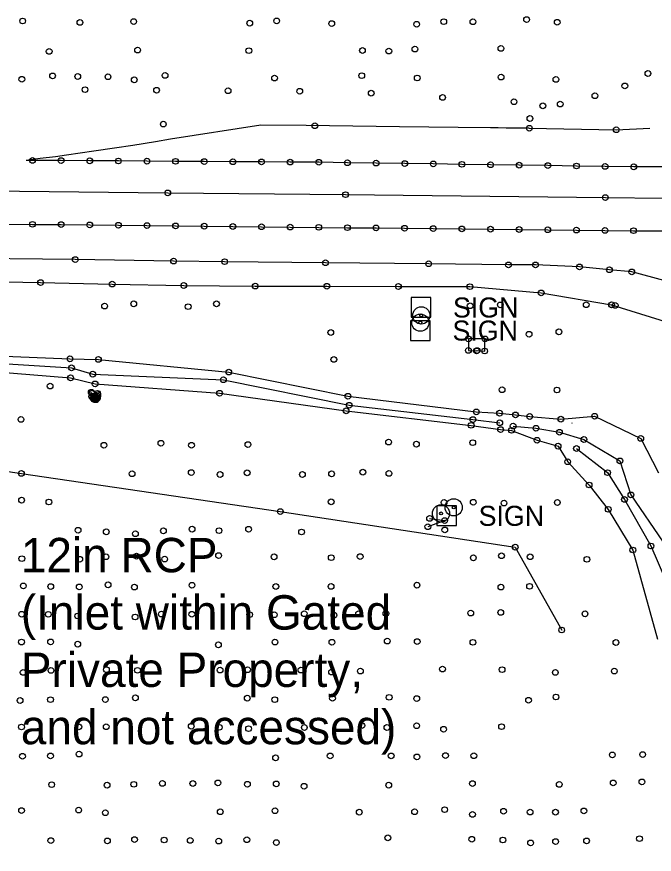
# Model space of a CAD drawing. Extents: x 20503438 to 20508873, y 7964251 to 7984667.
# Drawn here: x 20505829.6 to 20506052.3, y 7970315.8 to 7970608.1 of the extents above; entities that cross this region are included whole.
import ezdxf

# ---------------------------------------------------------------- set-up
doc = ezdxf.new("R2010")
doc.units = 0
for name, color, linetype in [('SurBreakLine', 7, 'Continuous'), ('SurConcreteSlab', 7, 'Continuous'), ('SurDrainageArrowDown', 7, 'Continuous'), ('SurDrainageArrowUp', 7, 'Continuous'), ('SurEdgeShoulderPaved', 7, 'Continuous'), ('SurEdgeShoulderUnpaved', 7, 'Continuous'), ('SurFenceChainLink', 7, 'Continuous'), ('SurMiscStructureLine', 7, 'Continuous'), ('SurPointsNonDTM', 7, 'Continuous'), ('SurRoadPoints', 7, 'Continuous'), ('SurSurveyPoints', 7, 'Continuous'), ('SurTopOfWater', 7, 'Continuous'), ('SurTxtDrainage', 7, 'Continuous')]:
    doc.layers.add(name, color=color, linetype=linetype)

msp = doc.modelspace()

# ---------------------------------------------------------------- linework, layer by layer
at = {"layer": 'SurBreakLine'}
for points in [[(20505659.98, 7970549.19), (20505725.91, 7970548.38), (20505788.99, 7970547.63), (20505882.34, 7970546.59), (20505944.46, 7970545.97), (20506035.17, 7970544.95), (20506055.65, 7970544.73), (20506135.76, 7970544.03), (20506246.7, 7970542.7), (20506314.1, 7970541.94), (20506377.13, 7970541.22), (20506448.59, 7970540.63), (20506494, 7970540.08), (20506513.48, 7970539.53), (20506534.35, 7970539.62)], [(20505710.77, 7970497.54), (20505732.85, 7970495.46), (20505756.48, 7970493.37), (20505802.57, 7970490.52), (20505848.21, 7970488.68), (20505858.14, 7970488.46), (20505903.67, 7970484.04), (20505945.27, 7970475.61), (20505990.11, 7970470.17), (20505998.24, 7970469.71), (20506003.81, 7970469.11), (20506008.75, 7970468.56), (20506019.64, 7970467.63), (20506031.44, 7970468.66), (20506047.52, 7970460.92), (20506053.76, 7970448.87)], [(20505711.46, 7970490.59), (20505731.01, 7970491.18), (20505758.81, 7970489.68), (20505801.32, 7970485.94), (20505848.43, 7970482.04), (20505856.97, 7970479.93), (20505900.46, 7970476.68), (20505944.64, 7970470.53), (20505988.31, 7970465.47), (20505998.59, 7970464), (20506002.44, 7970463.73), (20506011.31, 7970460.28), (20506018.66, 7970458.21), (20506022.02, 7970452.76), (20506029.51, 7970444.65), (20506036.2, 7970436.16), (20506044.77, 7970421.97), (20506053.42, 7970390.9)], [(20505857.84, 7970475.58), (20505857.72, 7970474.82), (20505857.29, 7970474.41), (20505856.69, 7970474.5), (20505856.27, 7970474.81), (20505855.82, 7970475.52), (20505855.65, 7970477.02)], [(20506002.96, 7970465.21), (20506010.95, 7970464.45), (20506019.15, 7970463.07), (20506027.69, 7970460.54), (20506040.26, 7970453.07), (20506044.1, 7970441.21), (20506055.37, 7970424.69), (20506067.63, 7970400.85), (20506090.73, 7970364.86), (20506121.5, 7970310.22), (20506143.59, 7970262.18), (20506176.03, 7970210.91), (20506203.05, 7970164.06), (20506235.78, 7970108.78), (20506259.31, 7970069.25), (20506303.96, 7969999.09)]]:
    msp.add_lwpolyline(points, dxfattribs=at)
at = {"layer": 'SurConcreteSlab'}
for points in [[(20506008.62, 7970569.15), (20506005.9, 7970569.17), (20506000.48, 7970569.22), (20505997.76, 7970569.24), (20505995.05, 7970569.27), (20505983.76, 7970569.4), (20505963.23, 7970569.67), (20505930.73, 7970570.05), (20505914.91, 7970570.2), (20505883.34, 7970565.3), (20505878.07, 7970564.42), (20505870.19, 7970563.15), (20505863.71, 7970562.15), (20505856.57, 7970561.09), (20505847.04, 7970559.75), (20505843.1, 7970559.22), (20505837.75, 7970558.53), (20505832.94, 7970557.93)], [(20506008.62, 7970569.15), (20506038.99, 7970568.62), (20506050.68, 7970569.22)], [(20506055.09, 7970555.65), (20506045.09, 7970555.68), (20506035.09, 7970555.82), (20506025.09, 7970555.97), (20506015.09, 7970556.11), (20506005.09, 7970556.26), (20505995.09, 7970556.4), (20505985.09, 7970556.55), (20505975.09, 7970556.69), (20505965.1, 7970556.83), (20505955.1, 7970556.98), (20505945.1, 7970557.12), (20505935.1, 7970557.26), (20505925.1, 7970557.32), (20505915.1, 7970557.39), (20505905.1, 7970557.45), (20505895.1, 7970557.52), (20505885.1, 7970557.59), (20505875.1, 7970557.65), (20505865.1, 7970557.72), (20505855.1, 7970557.78), (20505845.1, 7970557.85), (20505835.1, 7970557.92), (20505832.94, 7970557.93)], [(20505825.12, 7970535.72), (20505835.12, 7970535.61), (20505845.11, 7970535.51), (20505855.11, 7970535.4), (20505865.11, 7970535.3), (20505875.1, 7970535.19), (20505885.1, 7970535.08), (20505895.1, 7970534.98), (20505905.09, 7970534.87), (20505915.09, 7970534.77), (20505925.09, 7970534.66), (20505935.08, 7970534.56), (20505945.08, 7970534.45), (20505955.08, 7970534.35), (20505965.07, 7970534.24), (20505975.07, 7970534.14), (20505985.07, 7970534.03), (20505995.06, 7970533.92), (20506005.06, 7970533.82), (20506015.05, 7970533.71), (20506025.05, 7970533.61), (20506035.05, 7970533.5), (20506045.04, 7970533.4), (20506055.04, 7970533.3)], [(20505857.77, 7970476.64), (20505857.55, 7970475.22), (20505857.26, 7970474.83), (20505856.78, 7970474.8), (20505856.5, 7970474.91), (20505855.89, 7970476.65), (20505855.88, 7970475.71), (20505856.35, 7970474.81), (20505856.92, 7970474.72), (20505857.33, 7970474.73), (20505857.65, 7970474.96), (20505857.81, 7970475.61), (20505857.92, 7970476.17)]]:
    msp.add_lwpolyline(points, dxfattribs=at)
msp.add_lwpolyline([(20505993.14, 7970495.64), (20505987.36, 7970495.62), (20505987.35, 7970491.61), (20505990.21, 7970491.44), (20505990.39, 7970491.57), (20505993.03, 7970491.41)], close=True, dxfattribs=at)
at = {"layer": 'SurDrainageArrowDown'}
msp.add_lwpolyline([(20506025.08, 7970457.4), (20506035.95, 7970448.96), (20506041.86, 7970439.61), (20506051.09, 7970423.37), (20506062.05, 7970398.08), (20506083.83, 7970361.77), (20506117.02, 7970306.88), (20506136.1, 7970258.71), (20506172.77, 7970209.71), (20506199.46, 7970161.39), (20506230.82, 7970104.99), (20506255.2, 7970065.03), (20506302.09, 7969997.91), (20506332.16, 7969947.08), (20506370.3, 7969883.15), (20506398.2, 7969834.55), (20506432.94, 7969784.54)], dxfattribs=at)
at = {"layer": 'SurDrainageArrowUp'}
msp.add_lwpolyline([(20505588.51, 7970507.81), (20505597.53, 7970506.94), (20505614.51, 7970502.19), (20505635.08, 7970498.83), (20505655.93, 7970496.49), (20505678.23, 7970494.58), (20505682.9, 7970493.73), (20505711.11, 7970493.62), (20505731.16, 7970493.62), (20505757.46, 7970492.01), (20505802.13, 7970488.46), (20505848.74, 7970485.55), (20505856.14, 7970483.32), (20505901.79, 7970481.39), (20505945.72, 7970472.48), (20505988.92, 7970467.48), (20505998.29, 7970466.36)], dxfattribs=at)
at = {"layer": 'SurEdgeShoulderPaved'}
msp.add_lwpolyline([(20506056.08, 7970515.88), (20506044.41, 7970519.01), (20506036.59, 7970519.75), (20506026.15, 7970520.74), (20506010.77, 7970521.44), (20506001.36, 7970521.44), (20505973.47, 7970521.86), (20505937.45, 7970522.2), (20505902.22, 7970522.58), (20505884.4, 7970522.79), (20505850.04, 7970523.3), (20505804.42, 7970523.81), (20505772.68, 7970524.16), (20505723.75, 7970524.74), (20505698.34, 7970525.01)], dxfattribs=at)
at = {"layer": 'SurEdgeShoulderUnpaved'}
msp.add_lwpolyline([(20505583.75, 7970522.72), (20505588.05, 7970521.67), (20505613.04, 7970520.89), (20505638.02, 7970520.1), (20505663.01, 7970519.31), (20505687.99, 7970518.52), (20505712.98, 7970517.9), (20505737.97, 7970517.38), (20505762.96, 7970516.86), (20505787.95, 7970516.34), (20505812.95, 7970515.82), (20505837.94, 7970515.3), (20505862.93, 7970514.78), (20505887.92, 7970514.26), (20505912.91, 7970514.05), (20505937.9, 7970513.99), (20505962.89, 7970513.93), (20505987.89, 7970513.87), (20506012.76, 7970511.67), (20506037.35, 7970507.53), (20506060.92, 7970500.21), (20506079.1, 7970483.65), (20506094.14, 7970463.86), (20506101.05, 7970448.2)], dxfattribs=at)
at = {"layer": 'SurFenceChainLink'}
msp.add_lwpolyline([(20505563.79, 7970488.13), (20505618.36, 7970480.42), (20505698.84, 7970468.55), (20505760.89, 7970459.22), (20505831.24, 7970448.68), (20505921.66, 7970435.36), (20506003.71, 7970422.97), (20506019.92, 7970394.05)], dxfattribs=at)
at = {"layer": 'SurMiscStructureLine'}
msp.add_lwpolyline([(20505973.8, 7970432.99), (20505979.06, 7970432.22), (20505973.17, 7970430.1)], dxfattribs=at)
at = {"layer": 'SurPointsNonDTM'}
for centre in [(20505831.24, 7970448.68), (20505921.66, 7970435.36), (20505973.8, 7970432.99), (20505979.06, 7970432.22), (20505973.17, 7970430.1), (20506003.71, 7970422.97), (20506019.92, 7970394.05)]:
    msp.add_circle(centre, 1, dxfattribs=at)
at = {"layer": 'SurRoadPoints'}
for points in [[(20505970.75, 7970503.17), (20505970.75, 7970503.17), (20505974.18, 7970503.17), (20505974.18, 7970510.03), (20505967.32, 7970510.03), (20505967.32, 7970503.17), (20505970.75, 7970503.17)], [(20505970.57, 7970495.12), (20505970.57, 7970495.12), (20505974, 7970495.12), (20505974, 7970501.98), (20505967.14, 7970501.98), (20505967.14, 7970495.12), (20505970.57, 7970495.12)], [(20505979.71, 7970430.47), (20505979.71, 7970430.47), (20505983.14, 7970430.47), (20505983.14, 7970437.33), (20505976.28, 7970437.33), (20505976.28, 7970430.47), (20505979.71, 7970430.47)]]:
    msp.add_lwpolyline(points, dxfattribs=at)
for centre, radius in [((20505970.89, 7970503.83), 3), ((20505970.56, 7970501.31), 3), ((20505970.89, 7970503.83), 0.5), ((20505970.56, 7970501.31), 0.5), ((20505982.21, 7970436.84), 3), ((20505977.79, 7970434.74), 3), ((20505977.79, 7970434.74), 0.5), ((20505982.21, 7970436.84), 0.5)]:
    msp.add_circle(centre, radius, dxfattribs=at)
at = {"layer": 'SurSurveyPoints'}
for centre in [(20506007.66, 7970607.05), (20505831.68, 7970606.57), (20505851.69, 7970606.06), (20505870.45, 7970606.36), (20505910.98, 7970605.82), (20505920.39, 7970606.6), (20505939.61, 7970605.65), (20505969.28, 7970605.44), (20505978.72, 7970606.33), (20505988.93, 7970606.3), (20506018.36, 7970606.13), (20505840.94, 7970595.96), (20505871.82, 7970596.41), (20505910.66, 7970596.21), (20505950.35, 7970596.28), (20505959.55, 7970596.07), (20505968.68, 7970596.77), (20505998.7, 7970597.02), (20505831.39, 7970586.25), (20505842.14, 7970587.42), (20505850.92, 7970587.21), (20505861.48, 7970587.1), (20505881.4, 7970587.59), (20505919.64, 7970586.64), (20505950.09, 7970587.5), (20505969.48, 7970586.67), (20505998.76, 7970587), (20506017.91, 7970586.19), (20506050.04, 7970588.24), (20505870.66, 7970586.04), (20506041.98, 7970583.9), (20505853.45, 7970582.6), (20505878.44, 7970582.42), (20505903.43, 7970582.24), (20505928.43, 7970582.06), (20505953.4, 7970581.38), (20506031.53, 7970580.5), (20505978.34, 7970579.89), (20506003.27, 7970578.4), (20506019.41, 7970577.58), (20506013.34, 7970576.96), (20506008.82, 7970572.55), (20505880.8, 7970570.58), (20505933.71, 7970570.02), (20506008.62, 7970569.15), (20506008.62, 7970569.15), (20506038.99, 7970568.62), (20505835.1, 7970557.92), (20505845.1, 7970557.85), (20505855.1, 7970557.78), (20505865.1, 7970557.72), (20505875.1, 7970557.65), (20505885.1, 7970557.59), (20505895.1, 7970557.52), (20505905.1, 7970557.45), (20505915.1, 7970557.39), (20505925.1, 7970557.32), (20505935.1, 7970557.26), (20505945.1, 7970557.12), (20505955.1, 7970556.98), (20505965.1, 7970556.83), (20505975.09, 7970556.69), (20505985.09, 7970556.55), (20505995.09, 7970556.4), (20506005.09, 7970556.26), (20506015.09, 7970556.11), (20506025.09, 7970555.97), (20506035.09, 7970555.82), (20506045.09, 7970555.68), (20505882.34, 7970546.59), (20505944.46, 7970545.97), (20506035.17, 7970544.95), (20505835.12, 7970535.61), (20505845.11, 7970535.51), (20505855.11, 7970535.4), (20505865.11, 7970535.3), (20505875.1, 7970535.19), (20505885.1, 7970535.08), (20505895.1, 7970534.98), (20505905.09, 7970534.87), (20505915.09, 7970534.77), (20505925.09, 7970534.66), (20505935.08, 7970534.56), (20505945.08, 7970534.45), (20505955.08, 7970534.35), (20505965.07, 7970534.24), (20505975.07, 7970534.14), (20505985.07, 7970534.03), (20505995.06, 7970533.92), (20506005.06, 7970533.82), (20506015.05, 7970533.71), (20506025.05, 7970533.61), (20506035.05, 7970533.5), (20506045.04, 7970533.4), (20505850.04, 7970523.3), (20505884.4, 7970522.79), (20505902.22, 7970522.58), (20505937.45, 7970522.2), (20505973.47, 7970521.86), (20506001.36, 7970521.44), (20506010.77, 7970521.44), (20506026.15, 7970520.74), (20506036.59, 7970519.75), (20506044.41, 7970519.01), (20505837.94, 7970515.3), (20505862.93, 7970514.78), (20505887.92, 7970514.26), (20505912.91, 7970514.05), (20505937.9, 7970513.99), (20505962.89, 7970513.93), (20505987.89, 7970513.87), (20506012.76, 7970511.67), (20505870.48, 7970507.88), (20505899.38, 7970507.87), (20505998.49, 7970507.51), (20506028.49, 7970507.57), (20506037.35, 7970507.53), (20506038.6, 7970507.32), (20505860.3, 7970507.1), (20505889.47, 7970506.88), (20505987.96, 7970507.19), (20505939.29, 7970497.87), (20505987.36, 7970495.62), (20505993.14, 7970495.64), (20506008.53, 7970497.26), (20506018.96, 7970498.11), (20505987.35, 7970491.61), (20505990.21, 7970491.44), (20505990.39, 7970491.57), (20505993.03, 7970491.41), (20505848.21, 7970488.68), (20505858.14, 7970488.46), (20505940.36, 7970488.46), (20505848.74, 7970485.55), (20505903.67, 7970484.04), (20505848.43, 7970482.04), (20505856.14, 7970483.32), (20505901.79, 7970481.39), (20505841.27, 7970479.18), (20505856.97, 7970479.93), (20505855.65, 7970477.02), (20505855.82, 7970475.52), (20505855.88, 7970475.71), (20505855.89, 7970476.65), (20505857.55, 7970475.22), (20505857.77, 7970476.64), (20505857.81, 7970475.61), (20505857.84, 7970475.58), (20505857.92, 7970476.17), (20505900.46, 7970476.68), (20505945.27, 7970475.61), (20505999.11, 7970477.89), (20506018.28, 7970477.8), (20505856.27, 7970474.81), (20505856.35, 7970474.81), (20505856.5, 7970474.91), (20505856.69, 7970474.5), (20505856.78, 7970474.8), (20505856.92, 7970474.72), (20505857.26, 7970474.83), (20505857.29, 7970474.41), (20505857.33, 7970474.73), (20505857.65, 7970474.96), (20505857.72, 7970474.82), (20505945.72, 7970472.48), (20505944.64, 7970470.53), (20505990.11, 7970470.17), (20505998.24, 7970469.71), (20505831.09, 7970467.53), (20505988.92, 7970467.48), (20505998.29, 7970466.36), (20506003.81, 7970469.11), (20506008.75, 7970468.56), (20506019.64, 7970467.63), (20506031.44, 7970468.66), (20505988.31, 7970465.47), (20505998.59, 7970464), (20506002.44, 7970463.73), (20506002.96, 7970465.21), (20506010.95, 7970464.45), (20506019.15, 7970463.07), (20506027.69, 7970460.54), (20506047.52, 7970460.92), (20505860.07, 7970458.51), (20505879.96, 7970459.23), (20505890.64, 7970458.52), (20505910.36, 7970458.76), (20505959.48, 7970459.65), (20505969.2, 7970458.91), (20505988.86, 7970459.43), (20506011.31, 7970460.28), (20506018.66, 7970458.21), (20506025.08, 7970457.4), (20506022.02, 7970452.76), (20506040.26, 7970453.07), (20505890.57, 7970448.98), (20505910.09, 7970448.91), (20505950.48, 7970449.13), (20506035.95, 7970448.96), (20505869.88, 7970448.59), (20505900.62, 7970448.31), (20505929.37, 7970448.32), (20505939.57, 7970448.55), (20505959.59, 7970448.7), (20506029.51, 7970444.65), (20506044.1, 7970441.21), (20505831.32, 7970439.36), (20505840.86, 7970438.72), (20505939.42, 7970438.78), (20505978.84, 7970438.58), (20505989.04, 7970438.63), (20505999.78, 7970438.35), (20506018.41, 7970438.54), (20506041.86, 7970439.61), (20506036.2, 7970436.16), (20505851.04, 7970428.87), (20505880.84, 7970428.67), (20505890.85, 7970429.24), (20505900.25, 7970428.72), (20505910.59, 7970429.21), (20505979.1, 7970428.97), (20505860.88, 7970428.32), (20505871.05, 7970427.65), (20505929.07, 7970428.25), (20506051.09, 7970423.37), (20505860.76, 7970419.6), (20505871.43, 7970419.83), (20505900.11, 7970420.03), (20505919.48, 7970419.59), (20505949.55, 7970419.68), (20505998.91, 7970419.95), (20506008.91, 7970419.6), (20506044.77, 7970421.97), (20505831.39, 7970418.95), (20505851.6, 7970418.73), (20505881.28, 7970418.82), (20505939.46, 7970419.3), (20505989.07, 7970419.24), (20506028.74, 7970418.71), (20505831.92, 7970409.42), (20505841.49, 7970409.22), (20505851.45, 7970409.1), (20505861.51, 7970409.81), (20505870.7, 7970409.02), (20505890.81, 7970409.68), (20505920.1, 7970409.24), (20505939.38, 7970409.25), (20505969.39, 7970409.69), (20505998.71, 7970409.02), (20506008.71, 7970409.29), (20505831.34, 7970399.55), (20505840.64, 7970399.52), (20505880.11, 7970399.62), (20505890.76, 7970399.54), (20505910.95, 7970399.41), (20505919.57, 7970399.39), (20505930.03, 7970399.74), (20505940.37, 7970399.22), (20505948.98, 7970399.74), (20505958.53, 7970399.84), (20505988.16, 7970399.96), (20505998.65, 7970400.18), (20506028.07, 7970399.69), (20505850.9, 7970398.94), (20505870.94, 7970398.6), (20505831.28, 7970389.86), (20505841.42, 7970389.88), (20505850.9, 7970389.11), (20505900.03, 7970388.87), (20505919.8, 7970389.85), (20505939.7, 7970389.77), (20505959, 7970390.18), (20505969.47, 7970390), (20505988.93, 7970389.75), (20506038.86, 7970389.7), (20505831.84, 7970379.26), (20505841.57, 7970379.95), (20505860.91, 7970380.21), (20505871.78, 7970379.98), (20505900.63, 7970380.07), (20505910.23, 7970380.2), (20505928.86, 7970380.08), (20505939.58, 7970379.37), (20505949.64, 7970379.74), (20505978.3, 7970380.43), (20505999.09, 7970380.22), (20506017.71, 7970379.24), (20506038.31, 7970379.71), (20505871.06, 7970370.38), (20505910.13, 7970370.27), (20505939.88, 7970370.24), (20505959.67, 7970370.56), (20505969.31, 7970370.13), (20506017.93, 7970370.67), (20505830.77, 7970369.45), (20505841.41, 7970369.75), (20505860.56, 7970369.76), (20505919.7, 7970369.74), (20506008.35, 7970369.54), (20505831.28, 7970360.2), (20505851.3, 7970360.25), (20505860.86, 7970360.29), (20505890.55, 7970360.51), (20505900.36, 7970360.1), (20505910.57, 7970359.62), (20505930.05, 7970360.04), (20505950.14, 7970360.71), (20505958.89, 7970360.04), (20505969.27, 7970360.66), (20505978.69, 7970359.43), (20505998.95, 7970360.32), (20505831.62, 7970350.01), (20505841.4, 7970350.11), (20505851.38, 7970350.75), (20505920, 7970349.45), (20505939.07, 7970350.12), (20505960.38, 7970350.13), (20505969.37, 7970349.77), (20505979.35, 7970350.24), (20505989.25, 7970350.17), (20506037.62, 7970350.45), (20506048.21, 7970350.59), (20505899.86, 7970340.7), (20506037.92, 7970340.69), (20506047.94, 7970341.04), (20505841.81, 7970340.09), (20505861.17, 7970339.91), (20505870.49, 7970340.2), (20505880.48, 7970340.53), (20505891.11, 7970340.49), (20505910.16, 7970340.22), (20505920.24, 7970340.36), (20505929.95, 7970339.52), (20505959.51, 7970339.91), (20505988.76, 7970340.47), (20506019.08, 7970340.17), (20505831.29, 7970331.05), (20505851.24, 7970331.21), (20505860.56, 7970330.3), (20505900.68, 7970330.62), (20505919.81, 7970330.99), (20505949.23, 7970330.5), (20505968.56, 7970330.64), (20505979.05, 7970331.36), (20505988.77, 7970329.72), (20505999.62, 7970330.82), (20506008.9, 7970330.53), (20506017.76, 7970330.5), (20506027.67, 7970330.91), (20505841.51, 7970320.58), (20505861.28, 7970320.47), (20505870.75, 7970320.91), (20505881.09, 7970320.78), (20505890.19, 7970320.65), (20505900.16, 7970320.41), (20505909.96, 7970320.86), (20505959.2, 7970321.54), (20505988.53, 7970321.02), (20505999.41, 7970320.77), (20506017.81, 7970320.22), (20506028.63, 7970320.47), (20506047.09, 7970321.24), (20505920.27, 7970319.88), (20506009.08, 7970319.74)]:
    msp.add_circle(centre, 1, dxfattribs=at)
at = {"layer": 'SurTopOfWater'}
for points in [[(20506023.5, 7970466.21), (20506023.54, 7970466.21), (20506023.54, 7970466.25), (20506023.5, 7970466.25)], [(20506023.52, 7970466.26), (20506023.52, 7970466.26), (20506023.52, 7970466.22), (20506023.52, 7970466.22)], [(20506023.52, 7970466.26), (20506023.52, 7970466.26), (20506023.52, 7970466.24), (20506023.52, 7970466.24)], [(20506023.52, 7970466.24), (20506023.52, 7970466.24), (20506023.52, 7970466.23), (20506023.52, 7970466.23)], [(20506023.52, 7970466.23), (20506023.52, 7970466.23), (20506023.52, 7970466.22), (20506023.52, 7970466.22)], [(20506043.91, 7970421.49), (20506043.95, 7970421.49), (20506043.95, 7970421.53), (20506043.91, 7970421.53)], [(20506043.93, 7970421.54), (20506043.93, 7970421.54), (20506043.93, 7970421.5), (20506043.93, 7970421.5)], [(20506043.93, 7970421.54), (20506043.93, 7970421.54), (20506043.93, 7970421.52), (20506043.93, 7970421.52)], [(20506043.93, 7970421.52), (20506043.93, 7970421.52), (20506043.93, 7970421.51), (20506043.93, 7970421.51)], [(20506043.93, 7970421.51), (20506043.93, 7970421.51), (20506043.93, 7970421.5), (20506043.93, 7970421.5)]]:
    msp.add_lwpolyline(points, close=True, dxfattribs=at)
for centre in [(20506023.51, 7970466.23), (20506023.52, 7970466.23), (20506023.53, 7970466.23), (20506043.92, 7970421.51), (20506043.93, 7970421.51), (20506043.94, 7970421.51)]:
    msp.add_arc(centre, 0.00586, 186.3566, 5.6839, dxfattribs=at)

# ---------------------------------------------------------------- texts
at = {"layer": 'SurRoadPoints'}
for p in [(20505981.96, 7970503.1), (20505981.78, 7970495.05), (20505990.92, 7970430.4)]:
    msp.add_text('SIGN', height=6.995, rotation=360, dxfattribs=at).set_placement(p)
at = {"layer": 'SurTxtDrainage'}
for s, p in [('12in RCP', (20505831.05, 7970414.19)), ('(Inlet within Gated', (20505831.05, 7970394.19)), ('Private Property, ', (20505831.05, 7970374.19)), ('and not accessed)', (20505831.05, 7970354.19))]:
    msp.add_text(s, height=12, dxfattribs=at).set_placement(p)

doc.saveas('drawing.dxf')
